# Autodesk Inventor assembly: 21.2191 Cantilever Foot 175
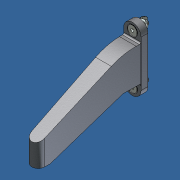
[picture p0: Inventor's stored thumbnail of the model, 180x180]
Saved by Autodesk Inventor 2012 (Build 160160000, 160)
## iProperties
Created: 2014-05
Part Number: 21.2191 Cantilever Foot 175
Document SubType Name: Assembly
Designer: Admin
Author: Admin
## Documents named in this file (4)
- C:\Andys Backup Data\ANDY'S INVENTOR\INVENTOR LIBRARIES\PARTS LIBRARY\FEET WHEELS FLOOR FASTENING SUPPORTS\21.2191 Cantilever Foot 175.iam
- C:\Andys Backup Data\ANDY'S INVENTOR\INVENTOR LIBRARIES\PARTS LIBRARY\FEET WHEELS FLOOR FASTENING SUPPORTS\SUBCOMPONENTS\21.2191 CANTILEVER FOOT 175.ipt
- C:\Andys Backup Data\ANDY'S INVENTOR\INVENTOR LIBRARIES\PARTS LIBRARY\FASTENING ELEMENTS\SCREWS COUNTERSUNK\21.1520 M8X25 CSUNK.IPT
- C:\Andys Backup Data\ANDY'S INVENTOR\INVENTOR LIBRARIES\PARTS LIBRARY\FASTENING ELEMENTS\NUTS\21.1351_2 M8 SQUARE NUT POS FXG.ipt
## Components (5 placed, 3 different names)
1. 21.2191 CANTILEVER FOOT 175:1 — Insert:1, Insert:2, Insert:3, Insert:4, Angle:1, Angle:2
2. 21.1520 M8x25 C'SUNK:1 — Insert:1
3. 21.1520 M8x25 C'SUNK:2 — Insert:2
4. 21.1351_2 M8 SQUARE NUT POS FXG:1 — Insert:3, Angle:2
5. 21.1351_2 M8 SQUARE NUT POS FXG:2 — Insert:4, Angle:1
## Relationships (6: Insert 4, Angle 2)
- Insert:1: 21.2191 CANTILEVER FOOT 175:1 ↔ 21.1520 M8x25 C'SUNK:1
- Insert:2: 21.2191 CANTILEVER FOOT 175:1 ↔ 21.1520 M8x25 C'SUNK:2
- Insert:3: 21.2191 CANTILEVER FOOT 175:1 ↔ 21.1351_2 M8 SQUARE NUT POS FXG:1
- Insert:4: 21.2191 CANTILEVER FOOT 175:1 ↔ 21.1351_2 M8 SQUARE NUT POS FXG:2
- Angle:1: 21.2191 CANTILEVER FOOT 175:1 ↔ 21.1351_2 M8 SQUARE NUT POS FXG:2
- Angle:2: 21.2191 CANTILEVER FOOT 175:1 ↔ 21.1351_2 M8 SQUARE NUT POS FXG:1
